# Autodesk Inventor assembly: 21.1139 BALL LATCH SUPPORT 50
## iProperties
Created: 2007-03
Part Number: 21.1139 BALL LATCH SUPPORT 50
Document SubType Name: Assembly
Designer: Andy Moles
Author: Andy Moles
